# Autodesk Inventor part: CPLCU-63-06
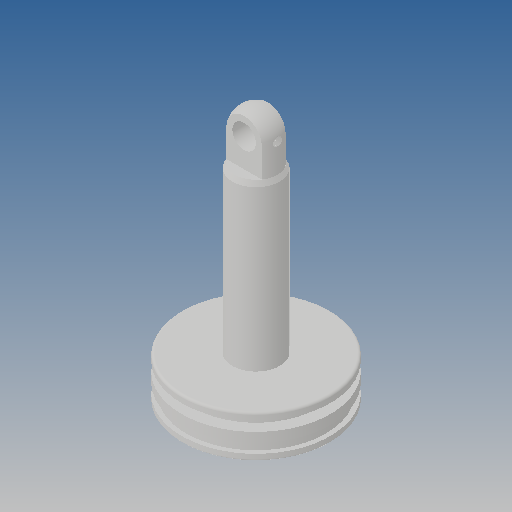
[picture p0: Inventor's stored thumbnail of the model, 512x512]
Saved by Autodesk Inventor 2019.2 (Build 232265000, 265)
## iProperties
Created: 2010-03
Part Number: CPLCU-63-06
Material: Ogólny
Document SubType Name: Modeling
Designer: CADENGINEERING4
Density: 1 g/cm^3
Appearance: Domyślna
Author: CADENGINEERING4
Revision Number: 3LAST_VERSION
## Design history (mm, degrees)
feature "Baza1"
node "Bryła1"
